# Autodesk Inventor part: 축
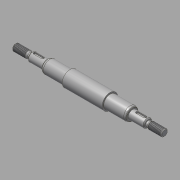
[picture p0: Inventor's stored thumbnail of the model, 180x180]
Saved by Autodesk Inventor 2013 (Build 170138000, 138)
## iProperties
Created: 2015-11
Part Number: 축
Material: 강철, 연강
Document SubType Name: Modeling
Designer: mduedu
Density: 1 g/cm^3
Author: mduedu
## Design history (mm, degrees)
sketch "스케치1"
  geometry: L1 (-86, 0)-(86, 0); L2 (-86, 0)-(-86, 4); L3 (-86, 4)-(-70.732, 4); L4 (-70.732, 4)-(-69, 3); L5 (-69, 3)-(-67, 3); L6 (-67, 3)-(-67, 5); L7 (-67, 5)-(-49, 5); L8 (-49, 5)-(-49, 6.55); L9 (-47.355, 7.5)-(-23, 7.5); L10 (-23, 7.5)-(-23, 9); L11 (0, 0)-(0, 9); L12 (86, 4)-(70.732, 4); L13 (70.732, 4)-(69, 3); L14 (69, 3)-(67, 3); L15 (67, 3)-(67, 5); L16 (67, 5)-(49, 5); L17 (23, 7.5)-(23, 9); L18 (86, 0)-(86, 4); L19 (-23, 9)-(23, 9); L20 (-49, 6.55)-(-47.355, 7.5); L21 (47.355, 7.5)-(23, 7.5); L22 (49, 6.55)-(47.355, 7.5); L23 (49, 5)-(49, 6.55); 1 further point
  constraints: 46 end point, 10 symmetric about line, 6 perpendicular, 5 parallel, 2 midpoint, 1 coincident, 1 horizontal
  dimensions: "d0" = 172 distance of L1.start L1.end (derived); "d1" = 8 diameter of L3 L1; "d2" = 30 deg angle of L4 L5; "d3" = 6 diameter of L5 L1; "d4" = 10 diameter of L7 L1; "d5" = 15 diameter of L9 L1; "d6" = 18 diameter of L19 L1; "d8" = 18 distance of L6.end L7.end; "d9" = 46 distance of L10.end L17.end; "d10" = 2 distance of L4.end L5.end; "d11" = 17 distance from line of L4.end L2; "d16" = 13.1 diameter of L8.end L1; "d17" = 30 deg angle of L20 L9; "d18" = 26 distance between parallel lines of L10 L8
revolve "회전1" sketch "스케치1" stored, may be unused: angle "d12" = 90 deg
chamfer "모따기1" distance "d13" = 1; stored, may be unused: second distance "d14" = 2, angle "d15" = 45 deg
fillet "모깎기1" dims "d19" = 4, "d20" = 0.5
node "작업 평면1"
sketch "스케치2" dims "d23" = 12
  geometry: L1 (-5.5, 1.5)-(3.5, 1.5); L2 (3.5, 1.5)-(3.5, -1.5); L3 (3.5, -1.5)-(-5.5, -1.5); L4 (-5.5, -1.5)-(-5.5, 1.5); L5 (-9, -4)-(-9, 4) reference; 3 further points
  constraints: 8 end point, 2 midpoint, 2 parallel, 2 vertical alignment, 1 horizontal, 1 perpendicular, 4 other
  dimensions: "d21" = 3 distance between parallel lines of L3 L1; "d24" = 2 dimension on L5
extrude "돌출1" cut sketch "스케치2" distance "d25" = 1.8; taper "d26" = 0 deg
feature "스레드1" dims "d27" = 10, "d28" = 0
feature "스레드2" dims "d29" = 10, "d30" = 0
chamfer "모따기2" distance "d31" = 1; stored, may be unused: second distance "d32" = 2, angle "d33" = 45 deg
fillet "모깎기2" dims "d34" = 0.3
node "솔리드1"
mirror "대칭1"
